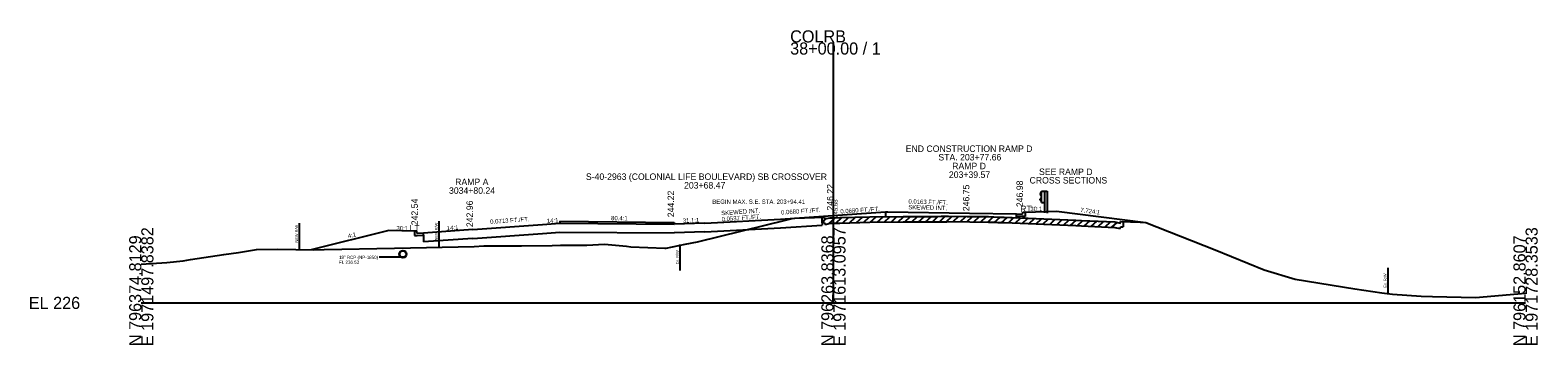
# Model space of a CAD drawing. Extents: x -26 to 1971766, y -10 to 796432.
# Drawn here: x -25.7 to 322.8, y 2490.3 to 2563 of the extents above; entities that cross this region are included whole.
import ezdxf

# ---------------------------------------------------------------- set-up
doc = ezdxf.new("R2010")
doc.units = 0
for name, color, linetype in [('BR_AUTO DIMENSION', 7, 'Continuous'), ('BR_BORDER LINES', 7, 'Continuous'), ('BR_CENTER LINE BASELINE', 7, 'Continuous'), ('BR_CENTER LINES', 7, 'Continuous'), ('BR_CONCRETE', 7, 'Continuous'), ('BR_DETAILS', 7, 'Continuous'), ('BR_PRESTRESSED BEAM', 7, 'Continuous'), ('BR_REBAR', 7, 'Continuous'), ('BR_TABLE LINES', 7, 'Continuous'), ('Default', 7, 'Continuous'), ('Level 31', 7, 'Continuous'), ('MISCELLANEOUS', 7, 'Continuous'), ('North Arrow', 7, 'Continuous'), ('RD_EX_Conc', 7, 'Continuous'), ('RD_EX_Road', 7, 'Continuous'), ('RD_HC_CL', 7, 'Continuous'), ('RD_HC_CL_Rel', 7, 'Continuous'), ('RD_PD_ALT1_TrvlWay', 7, 'Continuous'), ('RD_PD_ALT2_TnTmp', 7, 'Continuous'), ('RD_PD_CstnLmt', 7, 'Continuous'), ('RD_PD_Final_LnLine', 7, 'Continuous'), ('RD_PD_FOC', 7, 'Continuous'), ('RD_PD_MedBWall', 7, 'Continuous'), ('RD_PD_WallFill', 7, 'Continuous'), ('RD_SHT_IplotShp', 7, 'Continuous')]:
    doc.layers.add(name, color=color, linetype=linetype)

msp = doc.modelspace()

# ---------------------------------------------------------------- linework, layer by layer
at = {"layer": 'BR_AUTO DIMENSION'}
for p, q in [((160, 2500), (160, 2560.19)), ((0, 2500), (160, 2500)), ((160, 2500), (320, 2500))]:
    msp.add_line(p, q, dxfattribs=at)
at = {"layer": 'BR_BORDER LINES'}
msp.add_lwpolyline([(0, 2508.98), (5.92, 2509.36), (9.66, 2509.74), (11.41, 2510.02), (19.06, 2511.17), (22.46, 2511.68), (26.66, 2512.32), (31.53, 2512.38), (39.9, 2512.25), (42.31, 2512.35), (58.53, 2512.63), (76.94, 2513.07), (79.16, 2513.22), (87.86, 2513.17), (94.98, 2513.26), (96.88, 2513.31), (102.99, 2513.38), (107.09, 2513.55), (112.14, 2513.11), (113.17, 2512.97), (121.02, 2512.62), (121.32, 2512.61), (125.76, 2513.58), (128.58, 2514.09), (149.22, 2519.23), (150.48, 2519.54), (150.99, 2519.56), (157.92, 2519.81), (158.02, 2519.41), (158.36, 2519.48), (159.26, 2519.66), (160, 2519.68), (161.45, 2519.71), (168.38, 2519.88), (176.14, 2519.95), (179.7, 2519.97), (181.08, 2519.98), (183.63, 2520), (186.25, 2520.01), (186.59, 2520.06), (191.54, 2519.98), (195.81, 2519.94), (196.61, 2519.91), (197.07, 2519.87), (197.99, 2519.85), (199.48, 2519.8), (216.05, 2519.14), (217.35, 2519.08), (225.06, 2518.71), (226.26, 2518.44), (226.36, 2518.84), (230.94, 2518.65), (232.18, 2518.6), (248.21, 2512.23), (259.54, 2507.67), (266.76, 2505.46), (280.5, 2503.26), (286.79, 2502.3), (289.27, 2501.99), (295.86, 2501.52), (298.45, 2501.45), (308.4, 2501.21), (320, 2502.27)], dxfattribs=at)
at = {"layer": 'BR_CENTER LINE BASELINE'}
for p, q in [((157.36, 2518.54), (157.36, 2519.79)), ((157.36, 2518.54), (157.92, 2518.56)), ((157.92, 2518.56), (158.02, 2518.16)), ((158.02, 2518.16), (158.36, 2518.23)), ((158.36, 2518.23), (159.26, 2518.41)), ((159.26, 2518.41), (160, 2518.43)), ((160, 2518.43), (161.45, 2518.46)), ((161.45, 2518.46), (168.38, 2518.63)), ((168.38, 2518.63), (176.14, 2518.7)), ((176.14, 2518.7), (179.7, 2518.72)), ((179.7, 2518.72), (181.08, 2518.73)), ((181.08, 2518.73), (183.63, 2518.75)), ((183.63, 2518.75), (186.25, 2518.76)), ((186.25, 2518.76), (186.59, 2518.81)), ((186.59, 2518.81), (191.54, 2518.73)), ((191.54, 2518.73), (195.81, 2518.69)), ((195.81, 2518.69), (196.61, 2518.66)), ((196.61, 2518.66), (197.07, 2518.62)), ((197.07, 2518.62), (197.99, 2518.6)), ((197.99, 2518.6), (199.48, 2518.55)), ((199.48, 2518.55), (216.05, 2517.89)), ((216.05, 2517.89), (217.35, 2517.83)), ((217.35, 2517.83), (225.06, 2517.46)), ((225.06, 2517.46), (226.26, 2517.19)), ((226.26, 2517.19), (226.36, 2517.59)), ((226.36, 2517.59), (226.94, 2517.57)), ((226.94, 2518.82), (226.94, 2517.57))]:
    msp.add_line(p, q, dxfattribs=at)
at = {"layer": 'BR_CENTER LINES'}
msp.add_line((63.19, 2516.54), (57.19, 2516.74), dxfattribs=at)
at = {"layer": 'BR_DETAILS'}
for p, q in [((96.79, 2518.88), (96.79, 2518.4)), ((96.79, 2518.88), (123.16, 2518.55)), ((123.16, 2518.55), (123.16, 2518.22))]:
    msp.add_line(p, q, dxfattribs=at)
at = {"layer": 'BR_PRESTRESSED BEAM'}
for p, q in [((203.74, 2519.98), (202.32, 2520.07)), ((204.32, 2519.98), (203.74, 2519.98)), ((204.32, 2520.98), (204.32, 2519.98)), ((63.19, 2516.54), (63.19, 2515.54)), ((63.19, 2516.54), (63.19, 2515.54)), ((63.19, 2515.54), (63.78, 2515.54)), ((63.78, 2515.54), (65.2, 2515.62))]:
    msp.add_line(p, q, dxfattribs=at)
at = {"layer": 'BR_TABLE LINES'}
for p, q in [((124.5, 2513.49), (124.5, 2507.49)), ((288.13, 2508.13), (288.13, 2502.13))]:
    msp.add_line(p, q, dxfattribs=at)
at = {"layer": 'Level 31'}
for p, q in [((170.12, 2518.64), (171.47, 2519.91)), ((171.72, 2518.66), (173.06, 2519.92)), ((173.31, 2518.67), (174.66, 2519.94)), ((174.91, 2518.69), (176.25, 2519.95)), ((176.51, 2518.7), (177.84, 2519.96)), ((178.1, 2518.71), (179.44, 2519.97)), ((179.7, 2518.72), (181.04, 2519.98)), ((181.29, 2518.73), (182.64, 2520)), ((182.89, 2518.75), (184.23, 2520.01)), ((184.49, 2518.76), (185.82, 2520.01)), ((186.08, 2518.76), (187.45, 2520.05)), ((187.68, 2518.79), (188.98, 2520.02)), ((189.27, 2518.77), (190.58, 2520)), ((190.87, 2518.74), (192.18, 2519.97)), ((192.46, 2518.72), (193.78, 2519.96)), ((194.06, 2518.71), (195.38, 2519.94)), ((157.36, 2518.54), (158.35, 2519.48)), ((158.95, 2518.35), (160.38, 2519.69)), ((160.55, 2518.44), (161.91, 2519.72)), ((162.14, 2518.48), (163.51, 2519.76)), ((163.74, 2518.51), (165.1, 2519.8)), ((165.34, 2518.55), (166.7, 2519.84)), ((166.93, 2518.59), (168.3, 2519.87)), ((168.53, 2518.63), (169.87, 2519.89)), ((195.66, 2518.69), (196.92, 2519.88)), ((197.25, 2518.62), (198.54, 2519.83)), ((198.85, 2518.57), (200.13, 2519.77)), ((200.44, 2518.51), (201.72, 2519.71)), ((202.04, 2518.45), (203.32, 2519.65)), ((203.63, 2518.38), (204.91, 2519.58)), ((205.23, 2518.32), (206.51, 2519.52)), ((206.83, 2518.26), (208.1, 2519.46)), ((208.42, 2518.19), (209.7, 2519.39)), ((210.02, 2518.13), (211.29, 2519.33)), ((211.61, 2518.07), (212.89, 2519.27)), ((213.21, 2518), (214.49, 2519.2)), ((214.81, 2517.94), (216.08, 2519.14)), ((216.4, 2517.87), (217.67, 2519.07)), ((218, 2517.8), (219.26, 2518.99)), ((219.59, 2517.72), (220.86, 2518.91)), ((221.19, 2517.65), (222.45, 2518.84)), ((222.78, 2517.57), (224.05, 2518.76)), ((224.38, 2517.49), (225.56, 2518.6))]:
    msp.add_line(p, q, dxfattribs=at)
at = {"layer": 'MISCELLANEOUS'}
for p, q in [((168.38, 2519.88), (176.14, 2519.95)), ((176.14, 2519.95), (179.7, 2519.97)), ((179.7, 2519.97), (181.08, 2519.98)), ((181.08, 2519.98), (182.5, 2519.99)), ((182.5, 2519.99), (184.94, 2520.01)), ((184.94, 2520.01), (186.25, 2520.01)), ((186.25, 2520.01), (186.59, 2520.06)), ((186.59, 2520.06), (190.91, 2519.99)), ((190.91, 2519.99), (195.81, 2519.94)), ((195.81, 2519.94), (196.61, 2519.91)), ((196.61, 2519.91), (197.07, 2519.87)), ((157.36, 2519.79), (157.92, 2519.81)), ((157.36, 2519.79), (157.36, 2518)), ((157.92, 2519.81), (158.02, 2519.41)), ((158.02, 2519.41), (158.36, 2519.48)), ((158.36, 2519.48), (159.26, 2519.66)), ((159.26, 2519.66), (160, 2519.68)), ((160, 2519.68), (161.45, 2519.71)), ((161.45, 2519.71), (168.38, 2519.88)), ((197.07, 2519.87), (197.99, 2519.85)), ((197.99, 2519.85), (199.48, 2519.8)), ((199.48, 2519.8), (202.32, 2519.68))]:
    msp.add_line(p, q, dxfattribs=at)
at = {"layer": 'North Arrow'}
for p, q in [((147.74, 2519.38), (172, 2521.03)), ((172, 2521.03), (172, 2519.91)), ((172.59, 2521.05), (191.43, 2520.75)), ((191.43, 2520.75), (202.32, 2520.57)), ((76.67, 2516.96), (92.77, 2518.11)), ((130.29, 2518.45), (147.74, 2519.38))]:
    msp.add_line(p, q, dxfattribs=at)
at = {"layer": 'RD_EX_Conc'}
for p, q in [((202.32, 2520.59), (202.32, 2520.57)), ((202.32, 2520.57), (203.74, 2520.48)), ((203.74, 2520.48), (203.82, 2520.98)), ((203.82, 2520.98), (204.32, 2520.98)), ((63.69, 2516.54), (63.19, 2516.54)), ((63.69, 2516.54), (63.19, 2516.54)), ((63.78, 2516.04), (63.69, 2516.54)), ((63.78, 2516.04), (63.69, 2516.54)), ((65.2, 2516.12), (63.78, 2516.04)), ((65.2, 2516.14), (65.2, 2516.12))]:
    msp.add_line(p, q, dxfattribs=at)
at = {"layer": 'RD_EX_Road'}
for p, q in [((202.32, 2520.57), (202.32, 2520.59)), ((202.32, 2519.68), (202.32, 2520.57)), ((130.29, 2516.41), (123.16, 2516.18)), ((130.29, 2516.41), (147.74, 2517.34)), ((147.74, 2517.34), (157.36, 2518)), ((65.2, 2516.12), (65.2, 2516.14)), ((65.2, 2515.62), (65.2, 2516.12)), ((65.2, 2515.62), (65.2, 2514.1)), ((76.67, 2514.92), (65.2, 2514.1)), ((76.67, 2514.92), (92.77, 2516.07)), ((92.77, 2516.07), (96.79, 2516.36)), ((96.79, 2516.36), (123.16, 2516.18))]:
    msp.add_line(p, q, dxfattribs=at)
at = {"layer": 'RD_HC_CL'}
for p, q in [((208.09, 2525.64), (207.82, 2525.2)), ((207.82, 2525.2), (207.82, 2525.09)), ((207.82, 2525.09), (208.09, 2524.65)), ((207.82, 2523.94), (208.09, 2524.38)), ((207.82, 2523.83), (207.82, 2523.94)), ((208.09, 2523.39), (207.82, 2523.83)), ((208.09, 2525.8), (208.76, 2525.8)), ((208.09, 2523.23), (208.09, 2525.8)), ((208.76, 2525.8), (209.43, 2525.8)), ((208.76, 2525.8), (208.76, 2520.85)), ((209.43, 2525.8), (209.43, 2520.74)), ((208.09, 2523.23), (208.76, 2523.23))]:
    msp.add_line(p, q, dxfattribs=at)
at = {"layer": 'RD_PD_CstnLmt'}
for p, q in [((36.51, 2518.39), (36.51, 2512.39)), ((68.8, 2518.88), (68.8, 2512.88))]:
    msp.add_line(p, q, dxfattribs=at)
at = {"layer": 'RD_PD_Final_LnLine'}
for p, q in [((204.32, 2520.98), (211.57, 2521.23)), ((211.57, 2521.23), (232.18, 2518.6)), ((57.19, 2516.74), (39.28, 2512.26))]:
    msp.add_line(p, q, dxfattribs=at)
at = {"layer": 'RD_PD_FOC'}
msp.add_line((59.98, 2510.53), (54.98, 2510.53), dxfattribs=at)
for radius in [0.85, 0.75]:
    msp.add_circle((60.48, 2511.28), radius, dxfattribs=at)
at = {"layer": 'RD_PD_MedBWall'}
for p, q in [((172, 2521.03), (172.59, 2521.05)), ((76.67, 2516.96), (65.2, 2516.14)), ((92.77, 2518.11), (96.79, 2518.4)), ((96.79, 2518.4), (123.16, 2518.22)), ((130.29, 2518.45), (123.16, 2518.22))]:
    msp.add_line(p, q, dxfattribs=at)

# ---------------------------------------------------------------- texts
at = {"layer": 'BR_AUTO DIMENSION'}
for s, p in [('COLRB', (150, 2560.19)), ('38+00.00 / 1', (150, 2557.39)), ('EL 226', (-26, 2498.6))]:
    msp.add_text(s, height=2.8, dxfattribs=at).set_placement(p)
for s, p in [('E 1971497.8382', (2.8, 2490)), ('E 1971613.0957', (162.8, 2490)), ('E 1971728.3533', (322.8, 2490)), ('N 796374.8129', (0, 2490)), ('N 796263.8368', (160, 2490)), ('N 796152.8607', (320, 2490))]:
    msp.add_text(s, height=2.8, rotation=90, dxfattribs=at).set_placement(p)
at = {"layer": 'BR_CONCRETE'}
for s, rotation, p in [('0.0163 FT./FT.', 358.5753, (177.33, 2522.95)), ('80.4:1', 359.2872, (108.6, 2519.11)), ('SKEWED INT.', 3.9812, (134.09, 2520.25)), ('0.0537 FT./FT.', 3.9812, (134.19, 2518.84)), ('0.0680 FT./FT.', 3.8901, (147.93, 2520.4)), ('0.0680 FT./FT.', 3.8901, (161.63, 2520.64)), ('SKEWED INT.', 358.5753, (177.3, 2521.64)), ('30:1', 1.1458, (205.54, 2521.2)), ('7.724:1', 352.6232, (217.04, 2521.01)), ('30:1', 359.1385, (58.97, 2516.77)), ('0.0713 FT./FT.', 4.0808, (80.68, 2518.25)), ('14:1', 4.0808, (93.8, 2518.44)), ('31.1:1', 1.8401, (125.17, 2518.53)), ('4:1', 14.0362, (47.88, 2514.92))]:
    msp.add_text(s, height=1, rotation=rotation, dxfattribs=at).set_placement(p)
at = {"layer": 'BR_REBAR'}
for s, p in [('RT', (203.17, 2520.98)), ('LT', (62, 2516.54))]:
    msp.add_text(s, height=1.5, dxfattribs=at).set_placement(p)
at = {"layer": 'BR_TABLE LINES'}
for p in [(124.25, 2508.88), (287.88, 2503.51)]:
    msp.add_text('Ex. R/W ', height=0.65, rotation=90, dxfattribs=at).set_placement(p)
at = {"layer": 'Default'}
msp.add_text('242.54', height=1.5, rotation=90, dxfattribs=at).set_placement((63.94, 2517.95))
at = {"layer": 'RD_HC_CL_Rel'}
for s, p in [('246.22', (160, 2521.33)), (' 246.75', (191.43, 2520.64)), (' 246.98', (203.82, 2521.58)), (' 242.96', (76.67, 2516.96)), ('244.22', (123.16, 2519.81))]:
    msp.add_text(s, height=1.5, rotation=90, dxfattribs=at).set_placement(p)
at = {"layer": 'RD_PD_ALT1_TrvlWay'}
msp.add_text('14:1', height=1, rotation=4.0785, dxfattribs=at).set_placement((70.67, 2516.78))
at = {"layer": 'RD_PD_ALT2_TnTmp'}
for s, height, p in [('END CONSTRUCTION RAMP D', 1.5, (176.71, 2534.89)), ('STA. 203+77.66', 1.5, (184.26, 2532.92)), ('SEE RAMP D', 1.5, (207.53, 2529.55)), ('CROSS SECTIONS', 1.5, (205.34, 2527.59)), ('BEGIN MAX. S.E. STA. 203+94.41', 1, (132, 2522.89))]:
    msp.add_text(s, height=height, dxfattribs=at).set_placement(p)
at = {"layer": 'RD_PD_CstnLmt'}
for p in [(36.24, 2513.94), (68.53, 2514.44)]:
    msp.add_text('NEW R/W ', height=0.65, rotation=90, dxfattribs=at).set_placement(p)
at = {"layer": 'RD_PD_FOC'}
for s, p in [('18" RCP (NP-1850)', (45.7, 2510.15)), ('FL 236.53', (45.7, 2509.03))]:
    msp.add_text(s, height=0.75, dxfattribs=at).set_placement(p)
at = {"layer": 'RD_PD_WallFill'}
for s, p in [('203+39.57', (186.69, 2528.89)), ('RAMP D', (187.46, 2530.89)), ('RAMP A', (72.56, 2527.21)), ('S-40-2963 (COLONIAL LIFE BOULEVARD) SB CROSSOVER', (102.78, 2528.42)), ('203+68.47', (125.47, 2526.42)), ('3034+80.24', (71.13, 2525.21))]:
    msp.add_text(s, height=1.5, dxfattribs=at).set_placement(p)
at = {"layer": 'RD_SHT_IplotShp'}
msp.add_text('245.68', height=1, rotation=90, dxfattribs=at).set_placement((161, 2519.68))

doc.saveas('drawing.dxf')
